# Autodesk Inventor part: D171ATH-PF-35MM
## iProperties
Created: 2011-11
Part Number: D171ATH-PF-35MM
Document SubType Name: Modeling
Designer: D Cole
Density: 1 g/cm^3
Translation Standard: STEP AP214IS
File Name: P:\Fastrack\53972_CRANE 3D\Press Fit\D171A\THandle\35MM\Part73.stp
Preprocessor: Autodesk Inventor 2008
Postprocessor: Build: 342, Release: 2008 SP3 - Date: Tue 05/27/2008
Sent Units: MILLIMETERS
Uncertainty: 0.01
Author: D Cole
